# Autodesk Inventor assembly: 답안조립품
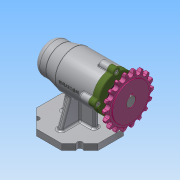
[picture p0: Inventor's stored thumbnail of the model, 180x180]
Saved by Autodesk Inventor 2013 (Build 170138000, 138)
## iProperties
Created: 2021-01
Part Number: 답안조립품
Document SubType Name: Assembly
Designer: Administrator
Author: Administrator
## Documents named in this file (12)
- C:\Users\Administrator\Desktop\710106V1027\답안조립품.iam
- C:\Users\Administrator\Desktop\710106V1027\본체.ipt
- C:\Users\Administrator\Desktop\710106V1027\베어링 6004.ipt
- C:\Users\Administrator\Desktop\710106V1027\볼트 M4.ipt
- C:\Users\Administrator\Desktop\710106V1027\커버.ipt
- C:\Users\Administrator\Desktop\710106V1027\오일 실.ipt
- C:\Users\Administrator\Desktop\710106V1027\축.ipt
- C:\Users\Administrator\Desktop\710106V1027\키 5 x 5 x 14.ipt
- C:\Users\Administrator\Desktop\710106V1027\스프로킷.ipt
- C:\Users\Administrator\Desktop\710106V1027\베어링 51202.ipt
- C:\Users\Administrator\Desktop\710106V1027\어댑터슬리브.ipt
- C:\Users\Administrator\Desktop\710106V1027\멈춤나사 M3.ipt
